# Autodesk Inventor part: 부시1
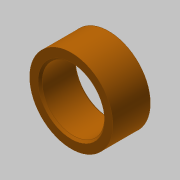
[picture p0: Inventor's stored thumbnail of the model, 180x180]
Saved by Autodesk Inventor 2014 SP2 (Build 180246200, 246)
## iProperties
Created: 2016-08
Part Number: 부시1
Material: 강철, 탄소
Document SubType Name: Modeling
Designer: mduedu
Density: 7.87 g/cm^3
Appearance: 주황색
Author: mduedu
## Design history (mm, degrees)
sketch "스케치1"
  geometry: C1 r 7.5 at (0, 0); C2 r 10 at (0, 0); 1 further point
  constraints: 2 centre point, 2 coincident
  dimensions: "d0" = 15 diameter of C1; "d1" = 20 diameter of C2
extrude "돌출1" new body sketch "스케치1" stored distance "d2" = 9; taper "d3" = 0 deg
chamfer "모따기1" distance "d4" = 0.5; stored, may be unused: second distance "d5" = 2, angle "d6" = 45 deg
node "솔리드1"
